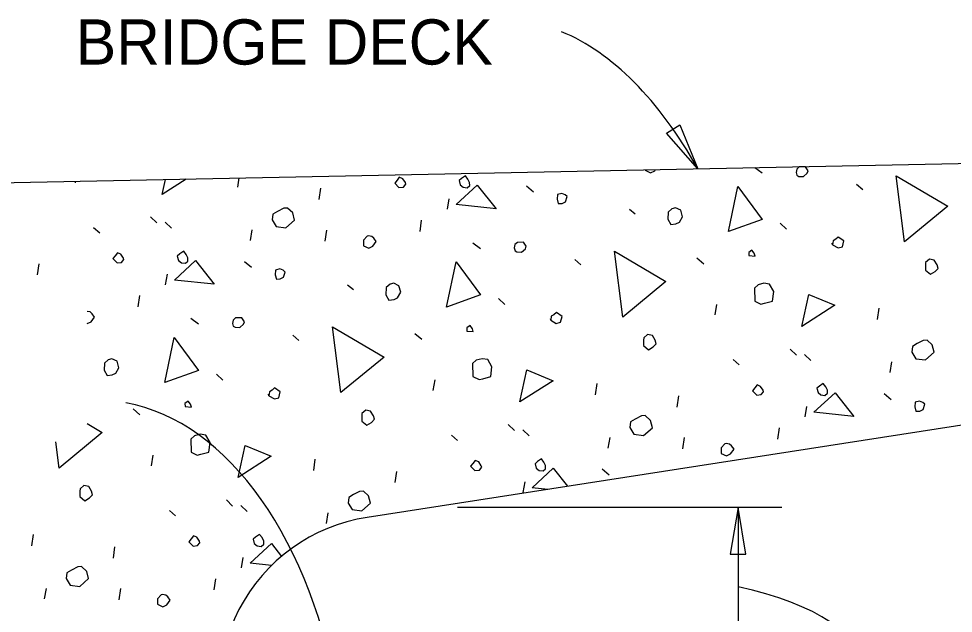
# Model space of a CAD drawing. Extents: x -1660015.2 to -1659984.9, y 2580594.2 to 2580616.7.
# Drawn here: x -1660011.876 to -1660008.753, y 2580612.631 to 2580614.619 of the extents above; entities that cross this region are included whole.
import ezdxf

# ---------------------------------------------------------------- set-up
doc = ezdxf.new("R2010")
doc.units = 0
for name, color, linetype in [('Miscellaneous', 7, 'Continuous'), ('Miscellaneous3', 7, 'Continuous'), ('PlotBorder_dp', 7, 'Continuous'), ('SheetLines_dp', 7, 'Continuous')]:
    doc.layers.add(name, color=color, linetype=linetype)

msp = doc.modelspace()

# ---------------------------------------------------------------- linework, layer by layer
at = {"layer": 'Miscellaneous'}
for p, q in [((-1660009.4157, 2580614.1214), (-1660009.3914, 2580614.1035)), ((-1660011.6862, 2580614.0709), (-1660011.6853, 2580614.076)), ((-1660011.1438, 2580614.0558), (-1660011.1393, 2580614.0869)), ((-1660010.8714, 2580614.0149), (-1660010.866, 2580614.0526)), ((-1660010.1796, 2580614.0605), (-1660010.1562, 2580614.0409)), ((-1660009.076, 2580614.0663), (-1660009.0557, 2580614.0485)), ((-1660010.4433, 2580613.9821), (-1660010.4372, 2580614.0173)), ((-1660009.8351, 2580613.982), (-1660009.8154, 2580613.9666)), ((-1660011.4356, 2580613.9569), (-1660011.4146, 2580613.9366)), ((-1660011.6254, 2580613.9216), (-1660011.6051, 2580613.9037)), ((-1660011.3868, 2580613.9389), (-1660011.3658, 2580613.9186)), ((-1660010.5348, 2580613.9084), (-1660010.5294, 2580613.9461)), ((-1660009.331, 2580613.9359), (-1660009.31, 2580613.9156)), ((-1660011.1013, 2580613.8782), (-1660011.0953, 2580613.9135)), ((-1660010.8521, 2580613.8751), (-1660010.8466, 2580613.9128)), ((-1660010.3589, 2580613.8701), (-1660010.3332, 2580613.8511)), ((-1660011.8132, 2580613.7625), (-1660011.8077, 2580613.8002)), ((-1660011.1214, 2580613.8081), (-1660011.098, 2580613.7885)), ((-1660010.0178, 2580613.814), (-1660009.9975, 2580613.7961)), ((-1660009.6104, 2580613.8196), (-1660009.587, 2580613.8)), ((-1660011.3851, 2580613.7297), (-1660011.379, 2580613.765)), ((-1660010.7768, 2580613.7296), (-1660010.7572, 2580613.7142)), ((-1660011.4766, 2580613.656), (-1660011.4712, 2580613.6937)), ((-1660010.2727, 2580613.6835), (-1660010.2518, 2580613.6633)), ((-1660009.549, 2580613.629), (-1660009.5429, 2580613.6643)), ((-1660009.0066, 2580613.6139), (-1660009.0011, 2580613.6516)), ((-1660011.3007, 2580613.6177), (-1660011.2749, 2580613.5988)), ((-1660010.9596, 2580613.5616), (-1660010.9393, 2580613.5438)), ((-1660010.5522, 2580613.5673), (-1660010.5288, 2580613.5476)), ((-1660009.2984, 2580613.515), (-1660009.2774, 2580613.4947)), ((-1660009.2496, 2580613.497), (-1660009.2286, 2580613.4767)), ((-1660009.4882, 2580613.4796), (-1660009.4679, 2580613.4618)), ((-1660008.9641, 2580613.4363), (-1660008.9581, 2580613.4716)), ((-1660011.2145, 2580613.4312), (-1660011.1935, 2580613.4109)), ((-1660010.4907, 2580613.3767), (-1660010.4847, 2580613.4119)), ((-1660009.9483, 2580613.3615), (-1660009.9429, 2580613.3992)), ((-1660009.676, 2580613.3206), (-1660009.6705, 2580613.3583)), ((-1660008.9842, 2580613.3662), (-1660008.9608, 2580613.3466)), ((-1660011.4939, 2580613.3149), (-1660011.4706, 2580613.2953)), ((-1660009.2479, 2580613.2878), (-1660009.2418, 2580613.3231)), ((-1660010.2402, 2580613.2626), (-1660010.2192, 2580613.2424)), ((-1660010.1914, 2580613.2447), (-1660010.1704, 2580613.2244)), ((-1660009.3394, 2580613.2141), (-1660009.334, 2580613.2518)), ((-1660010.43, 2580613.2273), (-1660010.4097, 2580613.2094)), ((-1660009.9059, 2580613.184), (-1660009.8999, 2580613.2192)), ((-1660009.6566, 2580613.1809), (-1660009.6512, 2580613.2186)), ((-1660011.4325, 2580613.1243), (-1660011.4264, 2580613.1596)), ((-1660010.8901, 2580613.1092), (-1660010.8847, 2580613.1469)), ((-1660009.926, 2580613.1139), (-1660009.9026, 2580613.0943)), ((-1660010.6177, 2580613.0683), (-1660010.6123, 2580613.106)), ((-1660010.1897, 2580613.0355), (-1660010.1836, 2580613.0707)), ((-1660011.182, 2580613.0103), (-1660011.161, 2580612.99)), ((-1660011.1331, 2580612.9923), (-1660011.1122, 2580612.972)), ((-1660011.3718, 2580612.9749), (-1660011.3515, 2580612.9571)), ((-1660010.8477, 2580612.9316), (-1660010.8416, 2580612.9669)), ((-1660011.8319, 2580612.8568), (-1660011.8265, 2580612.8945)), ((-1660011.5595, 2580612.8159), (-1660011.5541, 2580612.8536)), ((-1660011.1314, 2580612.7831), (-1660011.1254, 2580612.8184)), ((-1660011.223, 2580612.7094), (-1660011.2176, 2580612.7471)), ((-1660011.7895, 2580612.6793), (-1660011.7834, 2580612.7145)), ((-1660011.5402, 2580612.6762), (-1660011.5348, 2580612.7139))]:
    msp.add_line(p, q, dxfattribs=at)
for points in [[(-1660009.7821, 2580614.114), (-1660009.7821, 2580614.1127), (-1660009.7643, 2580614.1045), (-1660009.7505, 2580614.1108), (-1660009.7477, 2580614.1147)], [(-1660009.2754, 2580614.0957), (-1660009.2693, 2580614.0922), (-1660009.2535, 2580614.0912), (-1660009.241, 2580614.1024), (-1660009.2381, 2580614.1109), (-1660009.2468, 2580614.1241), (-1660009.2674, 2580614.1237), (-1660009.2758, 2580614.1163), (-1660009.278, 2580614.1054), (-1660009.2754, 2580614.0957)], [(-1660011.3166, 2580614.0833), (-1660011.3962, 2580614.0321)], [(-1660011.3962, 2580614.0321), (-1660011.3855, 2580614.082)], [(-1660010.6194, 2580614.0695), (-1660010.6052, 2580614.0552), (-1660010.5901, 2580614.0566), (-1660010.5824, 2580614.0665), (-1660010.5837, 2580614.0713), (-1660010.5924, 2580614.0845), (-1660010.604, 2580614.0891), (-1660010.6117, 2580614.0793), (-1660010.6194, 2580614.0695)], [(-1660010.4004, 2580614.0634), (-1660010.3906, 2580614.0557), (-1660010.3772, 2580614.0541), (-1660010.3688, 2580614.0616), (-1660010.369, 2580614.0719), (-1660010.3747, 2580614.0833), (-1660010.3827, 2580614.0941), (-1660010.3959, 2580614.0854), (-1660010.4043, 2580614.0779), (-1660010.4004, 2580614.0634)], [(-1660008.9157, 2580613.8738), (-1660008.9437, 2580614.094), (-1660008.7716, 2580613.9926), (-1660008.9157, 2580613.8738)], [(-1660010.4139, 2580613.9977), (-1660010.3434, 2580614.0632), (-1660010.2808, 2580613.9842), (-1660010.4139, 2580613.9977)], [(-1660009.5045, 2580613.9075), (-1660009.4725, 2580614.0584), (-1660009.3912, 2580613.9482), (-1660009.5045, 2580613.9075)], [(-1660010.077, 2580614.0155), (-1660010.0731, 2580614.001), (-1660010.0604, 2580614.0019), (-1660010.0489, 2580614.0075), (-1660010.0432, 2580614.0246), (-1660010.0499, 2580614.0305), (-1660010.0615, 2580614.0352), (-1660010.076, 2580614.0313), (-1660010.077, 2580614.0155)], [(-1660011.0291, 2580613.9467), (-1660011.0154, 2580613.9245), (-1660010.9832, 2580613.9202), (-1660010.9539, 2580613.9462), (-1660010.9604, 2580613.9703), (-1660010.9776, 2580613.9864), (-1660010.9904, 2580613.9856), (-1660011.0108, 2580613.975), (-1660011.0264, 2580613.9656), (-1660011.0291, 2580613.9467)], [(-1660009.7057, 2580613.9726), (-1660009.7072, 2580613.949), (-1660009.6971, 2580613.931), (-1660009.6796, 2580613.9331), (-1660009.6682, 2580613.9387), (-1660009.6576, 2580613.9571), (-1660009.6634, 2580613.9788), (-1660009.6811, 2580613.987), (-1660009.6932, 2580613.9838), (-1660009.7057, 2580613.9726)], [(-1660010.7236, 2580613.8785), (-1660010.7239, 2580613.8603), (-1660010.7061, 2580613.8521), (-1660010.6923, 2580613.8584), (-1660010.681, 2580613.8744), (-1660010.6891, 2580613.8852), (-1660010.6959, 2580613.8911), (-1660010.7068, 2580613.8933), (-1660010.7116, 2580613.8921), (-1660010.7236, 2580613.8785)], [(-1660009.1563, 2580613.8636), (-1660009.1379, 2580613.853), (-1660009.1234, 2580613.8569), (-1660009.1183, 2580613.8764), (-1660009.1373, 2580613.8894), (-1660009.1457, 2580613.882), (-1660009.1547, 2580613.877), (-1660009.1563, 2580613.8636), (-1660009.1576, 2580613.8685)], [(-1660010.2172, 2580613.8434), (-1660010.2111, 2580613.8398), (-1660010.1953, 2580613.8389), (-1660010.1827, 2580613.85), (-1660010.1799, 2580613.8585), (-1660010.1886, 2580613.8717), (-1660010.2092, 2580613.8714), (-1660010.2175, 2580613.864), (-1660010.2198, 2580613.853), (-1660010.2172, 2580613.8434)], [(-1660011.5612, 2580613.8171), (-1660011.547, 2580613.8028), (-1660011.5319, 2580613.8043), (-1660011.5242, 2580613.8141), (-1660011.5255, 2580613.8189), (-1660011.5342, 2580613.8321), (-1660011.5458, 2580613.8368), (-1660011.5535, 2580613.827), (-1660011.5612, 2580613.8171)], [(-1660011.3422, 2580613.8111), (-1660011.3323, 2580613.8034), (-1660011.319, 2580613.8018), (-1660011.3106, 2580613.8092), (-1660011.3108, 2580613.8195), (-1660011.3164, 2580613.8309), (-1660011.3245, 2580613.8417), (-1660011.3377, 2580613.833), (-1660011.3461, 2580613.8256), (-1660011.3422, 2580613.8111)], [(-1660009.8575, 2580613.6214), (-1660009.8855, 2580613.8417), (-1660009.7133, 2580613.7403), (-1660009.8575, 2580613.6214)], [(-1660009.4365, 2580613.8274), (-1660009.4152, 2580613.8253), (-1660009.4178, 2580613.835), (-1660009.4259, 2580613.8458), (-1660009.4366, 2580613.8377), (-1660009.4365, 2580613.8274)], [(-1660011.3556, 2580613.7454), (-1660011.2852, 2580613.8108), (-1660011.2226, 2580613.7319), (-1660011.3556, 2580613.7454)], [(-1660010.4463, 2580613.6552), (-1660010.4143, 2580613.8061), (-1660010.333, 2580613.6959), (-1660010.4463, 2580613.6552)], [(-1660008.8459, 2580613.7967), (-1660008.8462, 2580613.7785), (-1660008.8296, 2580613.7648), (-1660008.814, 2580613.7742), (-1660008.8038, 2580613.7847), (-1660008.8071, 2580613.7967), (-1660008.8164, 2580613.8124), (-1660008.8329, 2580613.8157), (-1660008.8454, 2580613.8046), (-1660008.8459, 2580613.7967)], [(-1660011.0188, 2580613.7632), (-1660011.0149, 2580613.7487), (-1660011.0022, 2580613.7495), (-1660010.9907, 2580613.7552), (-1660010.985, 2580613.7722), (-1660010.9917, 2580613.7782), (-1660011.0033, 2580613.7828), (-1660011.0178, 2580613.779), (-1660011.0188, 2580613.7632)], [(-1660010.6475, 2580613.7203), (-1660010.6489, 2580613.6966), (-1660010.6389, 2580613.6786), (-1660010.6214, 2580613.6807), (-1660010.6099, 2580613.6864), (-1660010.5993, 2580613.7047), (-1660010.6052, 2580613.7265), (-1660010.6229, 2580613.7347), (-1660010.635, 2580613.7314), (-1660010.6475, 2580613.7203)], [(-1660009.4177, 2580613.7186), (-1660009.4163, 2580613.6749), (-1660009.3955, 2580613.665), (-1660009.3835, 2580613.6682), (-1660009.3569, 2580613.6753), (-1660009.3526, 2580613.7075), (-1660009.3669, 2580613.7321), (-1660009.3858, 2580613.7349), (-1660009.4051, 2580613.7297), (-1660009.4177, 2580613.7186)], [(-1660009.259, 2580613.5902), (-1660009.236, 2580613.6974), (-1660009.1486, 2580613.6612), (-1660009.259, 2580613.5902)], [(-1660011.6475, 2580613.6), (-1660011.6341, 2580613.6061), (-1660011.6228, 2580613.622), (-1660011.6309, 2580613.6328), (-1660011.6376, 2580613.6388), (-1660011.6475, 2580613.6408)], [(-1660011.159, 2580613.591), (-1660011.1529, 2580613.5875), (-1660011.1371, 2580613.5865), (-1660011.1245, 2580613.5977), (-1660011.1216, 2580613.6062), (-1660011.1303, 2580613.6194), (-1660011.151, 2580613.619), (-1660011.1593, 2580613.6116), (-1660011.1616, 2580613.6007), (-1660011.159, 2580613.591)], [(-1660010.0981, 2580613.6113), (-1660010.0797, 2580613.6007), (-1660010.0652, 2580613.6046), (-1660010.0601, 2580613.6241), (-1660010.0791, 2580613.6371), (-1660010.0875, 2580613.6297), (-1660010.0965, 2580613.6247), (-1660010.0981, 2580613.6113), (-1660010.0994, 2580613.6161)], [(-1660010.7993, 2580613.3691), (-1660010.8272, 2580613.5893), (-1660010.6551, 2580613.4879), (-1660010.7993, 2580613.3691)], [(-1660010.3782, 2580613.575), (-1660010.357, 2580613.573), (-1660010.3596, 2580613.5826), (-1660010.3676, 2580613.5934), (-1660010.3784, 2580613.5854), (-1660010.3782, 2580613.575)], [(-1660011.3881, 2580613.4028), (-1660011.356, 2580613.5537), (-1660011.2748, 2580613.4435), (-1660011.3881, 2580613.4028)], [(-1660009.7877, 2580613.5443), (-1660009.788, 2580613.5262), (-1660009.7714, 2580613.5125), (-1660009.7558, 2580613.5218), (-1660009.7456, 2580613.5323), (-1660009.7489, 2580613.5444), (-1660009.7582, 2580613.56), (-1660009.7747, 2580613.5634), (-1660009.7872, 2580613.5522), (-1660009.7877, 2580613.5443)], [(-1660008.8919, 2580613.5048), (-1660008.8782, 2580613.4826), (-1660008.846, 2580613.4783), (-1660008.8167, 2580613.5043), (-1660008.8232, 2580613.5284), (-1660008.8404, 2580613.5445), (-1660008.8532, 2580613.5437), (-1660008.8736, 2580613.533), (-1660008.8892, 2580613.5237), (-1660008.8919, 2580613.5048)], [(-1660011.5893, 2580613.468), (-1660011.5907, 2580613.4443), (-1660011.5807, 2580613.4263), (-1660011.5632, 2580613.4284), (-1660011.5517, 2580613.434), (-1660011.5411, 2580613.4524), (-1660011.5469, 2580613.4741), (-1660011.5647, 2580613.4823), (-1660011.5767, 2580613.4791), (-1660011.5893, 2580613.468)], [(-1660010.3594, 2580613.4662), (-1660010.3581, 2580613.4226), (-1660010.3373, 2580613.4126), (-1660010.3252, 2580613.4158), (-1660010.2987, 2580613.423), (-1660010.2944, 2580613.4552), (-1660010.3087, 2580613.4798), (-1660010.3276, 2580613.4825), (-1660010.3469, 2580613.4773), (-1660010.3594, 2580613.4662)], [(-1660010.2008, 2580613.3379), (-1660010.1778, 2580613.445), (-1660010.0904, 2580613.4089), (-1660010.2008, 2580613.3379)], [(-1660009.424, 2580613.3752), (-1660009.4098, 2580613.3609), (-1660009.3947, 2580613.3624), (-1660009.387, 2580613.3722), (-1660009.3883, 2580613.377), (-1660009.397, 2580613.3902), (-1660009.4086, 2580613.3949), (-1660009.4163, 2580613.385), (-1660009.424, 2580613.3752)], [(-1660009.205, 2580613.3692), (-1660009.1952, 2580613.3615), (-1660009.1818, 2580613.3599), (-1660009.1734, 2580613.3673), (-1660009.1736, 2580613.3776), (-1660009.1792, 2580613.389), (-1660009.1873, 2580613.3998), (-1660009.2005, 2580613.3911), (-1660009.2089, 2580613.3837), (-1660009.205, 2580613.3692)], [(-1660011.0399, 2580613.3589), (-1660011.0215, 2580613.3483), (-1660011.007, 2580613.3522), (-1660011.0019, 2580613.3717), (-1660011.0209, 2580613.3847), (-1660011.0292, 2580613.3773), (-1660011.0383, 2580613.3723), (-1660011.0399, 2580613.3589), (-1660011.0411, 2580613.3638)], [(-1660009.2184, 2580613.3035), (-1660009.148, 2580613.3689), (-1660009.0854, 2580613.2899), (-1660009.2184, 2580613.3035)], [(-1660011.32, 2580613.3227), (-1660011.2988, 2580613.3206), (-1660011.3013, 2580613.3303), (-1660011.3094, 2580613.3411), (-1660011.3202, 2580613.333), (-1660011.32, 2580613.3227)], [(-1660008.8816, 2580613.3213), (-1660008.8777, 2580613.3068), (-1660008.865, 2580613.3076), (-1660008.8535, 2580613.3132), (-1660008.8478, 2580613.3303), (-1660008.8545, 2580613.3363), (-1660008.8661, 2580613.3409), (-1660008.8806, 2580613.337), (-1660008.8816, 2580613.3213)], [(-1660010.7295, 2580613.292), (-1660010.7298, 2580613.2738), (-1660010.7131, 2580613.2601), (-1660010.6975, 2580613.2695), (-1660010.6874, 2580613.28), (-1660010.6906, 2580613.292), (-1660010.7, 2580613.3077), (-1660010.7164, 2580613.311), (-1660010.729, 2580613.2999), (-1660010.7295, 2580613.292)], [(-1660011.6475, 2580613.2654), (-1660011.5969, 2580613.2356), (-1660011.7411, 2580613.1167)], [(-1660009.8337, 2580613.2525), (-1660009.82, 2580613.2303), (-1660009.7878, 2580613.226), (-1660009.7585, 2580613.2519), (-1660009.765, 2580613.2761), (-1660009.7822, 2580613.2922), (-1660009.7949, 2580613.2913), (-1660009.8154, 2580613.2807), (-1660009.831, 2580613.2713), (-1660009.8337, 2580613.2525)], [(-1660011.7411, 2580613.1167), (-1660011.7523, 2580613.2051)], [(-1660011.3012, 2580613.2139), (-1660011.2999, 2580613.1702), (-1660011.2791, 2580613.1603), (-1660011.267, 2580613.1635), (-1660011.2404, 2580613.1706), (-1660011.2361, 2580613.2028), (-1660011.2505, 2580613.2274), (-1660011.2693, 2580613.2302), (-1660011.2887, 2580613.225), (-1660011.3012, 2580613.2139)], [(-1660011.1426, 2580613.0855), (-1660011.1195, 2580613.1927), (-1660011.0322, 2580613.1565), (-1660011.1426, 2580613.0855)], [(-1660009.5281, 2580613.1843), (-1660009.5284, 2580613.1661), (-1660009.5107, 2580613.1579), (-1660009.4969, 2580613.1642), (-1660009.4856, 2580613.1801), (-1660009.4937, 2580613.1909), (-1660009.5004, 2580613.1968), (-1660009.5114, 2580613.1991), (-1660009.5162, 2580613.1978), (-1660009.5281, 2580613.1843)], [(-1660010.3658, 2580613.1229), (-1660010.3516, 2580613.1085), (-1660010.3365, 2580613.11), (-1660010.3287, 2580613.1198), (-1660010.33, 2580613.1247), (-1660010.3387, 2580613.1379), (-1660010.3503, 2580613.1425), (-1660010.3581, 2580613.1327), (-1660010.3658, 2580613.1229)], [(-1660010.1468, 2580613.1168), (-1660010.1369, 2580613.1091), (-1660010.1236, 2580613.1075), (-1660010.1152, 2580613.1149), (-1660010.1154, 2580613.1253), (-1660010.121, 2580613.1367), (-1660010.1291, 2580613.1475), (-1660010.1423, 2580613.1387), (-1660010.1506, 2580613.1313), (-1660010.1468, 2580613.1168)], [(-1660010.1602, 2580613.0511), (-1660010.0898, 2580613.1166), (-1660010.0419, 2580613.0561)], [(-1660011.6712, 2580613.0397), (-1660011.6715, 2580613.0215), (-1660011.6549, 2580613.0078), (-1660011.6393, 2580613.0171), (-1660011.6292, 2580613.0276), (-1660011.6324, 2580613.0397), (-1660011.6418, 2580613.0553), (-1660011.6582, 2580613.0587), (-1660011.6708, 2580613.0475), (-1660011.6712, 2580613.0397)], [(-1660010.1081, 2580613.0458), (-1660010.1602, 2580613.0511)], [(-1660010.7755, 2580613.0001), (-1660010.7618, 2580612.9779), (-1660010.7296, 2580612.9736), (-1660010.7003, 2580612.9996), (-1660010.7067, 2580613.0237), (-1660010.724, 2580613.0398), (-1660010.7367, 2580613.039), (-1660010.7572, 2580613.0283), (-1660010.7728, 2580613.019), (-1660010.7755, 2580613.0001)], [(-1660011.3076, 2580612.8705), (-1660011.2934, 2580612.8562), (-1660011.2782, 2580612.8577), (-1660011.2705, 2580612.8675), (-1660011.2718, 2580612.8723), (-1660011.2805, 2580612.8855), (-1660011.2921, 2580612.8902), (-1660011.2998, 2580612.8803), (-1660011.3076, 2580612.8705)], [(-1660011.0885, 2580612.8645), (-1660011.0787, 2580612.8568), (-1660011.0653, 2580612.8552), (-1660011.057, 2580612.8626), (-1660011.0571, 2580612.8729), (-1660011.0628, 2580612.8843), (-1660011.0709, 2580612.8951), (-1660011.0841, 2580612.8864), (-1660011.0924, 2580612.879), (-1660011.0885, 2580612.8645)], [(-1660011.102, 2580612.7988), (-1660011.0315, 2580612.8642), (-1660010.9978, 2580612.8216)], [(-1660011.0308, 2580612.7915), (-1660011.102, 2580612.7988)], [(-1660011.7173, 2580612.7478), (-1660011.7035, 2580612.7256), (-1660011.6713, 2580612.7213), (-1660011.6421, 2580612.7472), (-1660011.6485, 2580612.7714), (-1660011.6658, 2580612.7875), (-1660011.6785, 2580612.7866), (-1660011.6989, 2580612.776), (-1660011.7145, 2580612.7666), (-1660011.7173, 2580612.7478)], [(-1660011.4117, 2580612.6796), (-1660011.412, 2580612.6614), (-1660011.3943, 2580612.6532), (-1660011.3804, 2580612.6595), (-1660011.3692, 2580612.6754), (-1660011.3772, 2580612.6862), (-1660011.384, 2580612.6921), (-1660011.395, 2580612.6944), (-1660011.3998, 2580612.6931), (-1660011.4117, 2580612.6796)]]:
    msp.add_lwpolyline(points, dxfattribs=at)
at = {"layer": 'Miscellaneous3'}
for p, q in [((-1660014.6931, 2580614.0158), (-1660004.5045, 2580614.2196)), ((-1660007.4989, 2580613.4513), (-1660010.7113, 2580612.9521))]:
    msp.add_line(p, q, dxfattribs=at)
msp.add_arc((-1660010.6217, 2580612.3757), 0.5833, 98.8325, 206.4422, dxfattribs=at)
at = {"layer": 'SheetLines_dp'}
for p, q in [((-1660009.3262, 2580612.9853), (-1660010.4096, 2580612.9853)), ((-1660009.4721, 2580612.9853), (-1660009.4721, 2580612.4534))]:
    msp.add_line(p, q, dxfattribs=at)
for points in [[(-1660009.6066, 2580614.1174), (-1660009.7112, 2580614.2364), (-1660009.6662, 2580614.2642)], [(-1660009.4721, 2580612.9852), (-1660009.4985, 2580612.829), (-1660009.4456, 2580612.829)]]:
    msp.add_lwpolyline(points, close=True, dxfattribs=at)
for centre, major_axis, ratio, start_param, end_param in [((-1660010.3517, 2580612.2487), (-0.1111, -2.3674), 0.464296, 2.502126, 2.976953), ((-1660011.5969, 2580612.0226), (0.0174, -1.3204), 0.616683, 1.795781, 3.022833), ((-1660009.8313, 2580612.436), (-0.7827, 0), 0.407451, 3.141527, 4.235533)]:
    msp.add_ellipse(centre, major_axis=major_axis, ratio=ratio, start_param=start_param, end_param=end_param, dxfattribs=at)

# ---------------------------------------------------------------- texts
at = {"layer": 'PlotBorder_dp'}
msp.add_text('BRIDGE DECK', height=0.1512, dxfattribs=at).set_placement((-1660011.6849, 2580614.4659))

doc.saveas('drawing.dxf')
